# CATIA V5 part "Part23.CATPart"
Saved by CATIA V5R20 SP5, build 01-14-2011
Part number: Part23
Material "Water": density 1000 kg/m3
Bounding box of the stored display mesh (mm): x -1.919 to 1.919, y -2 to 2, z -1.919 to 1.919
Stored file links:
  D:\新建文件夹\Part23.CATPart
  C:\Program Files\Dassault Systemes\B20\intel_a\startup\materials\Catalog.CATMaterial
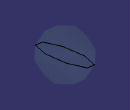
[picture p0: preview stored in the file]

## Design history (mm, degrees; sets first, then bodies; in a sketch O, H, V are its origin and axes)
Body1 (main body), material "Water"
  Sketch1 on xy-plane, origin (0, 0, 0), H (1, 0, 0), V (0, 1, 0)
    arc A1 centre (0, 0) radius 2 from (0, -2) to (0, 2) ccw
    axis line L1 (0, 5.9256) -> (0, -6.5373)
    point P1 (0, 5.9256)
    point P3 (0, 2)
    point P4 (0, -2)
    radius A1 = 2
    coincidence: P1 V, L1 P3, L1 P4
    vertical: L1 V
  Shaft1: profile Sketch1, axis Sketch1.L1, angle 360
